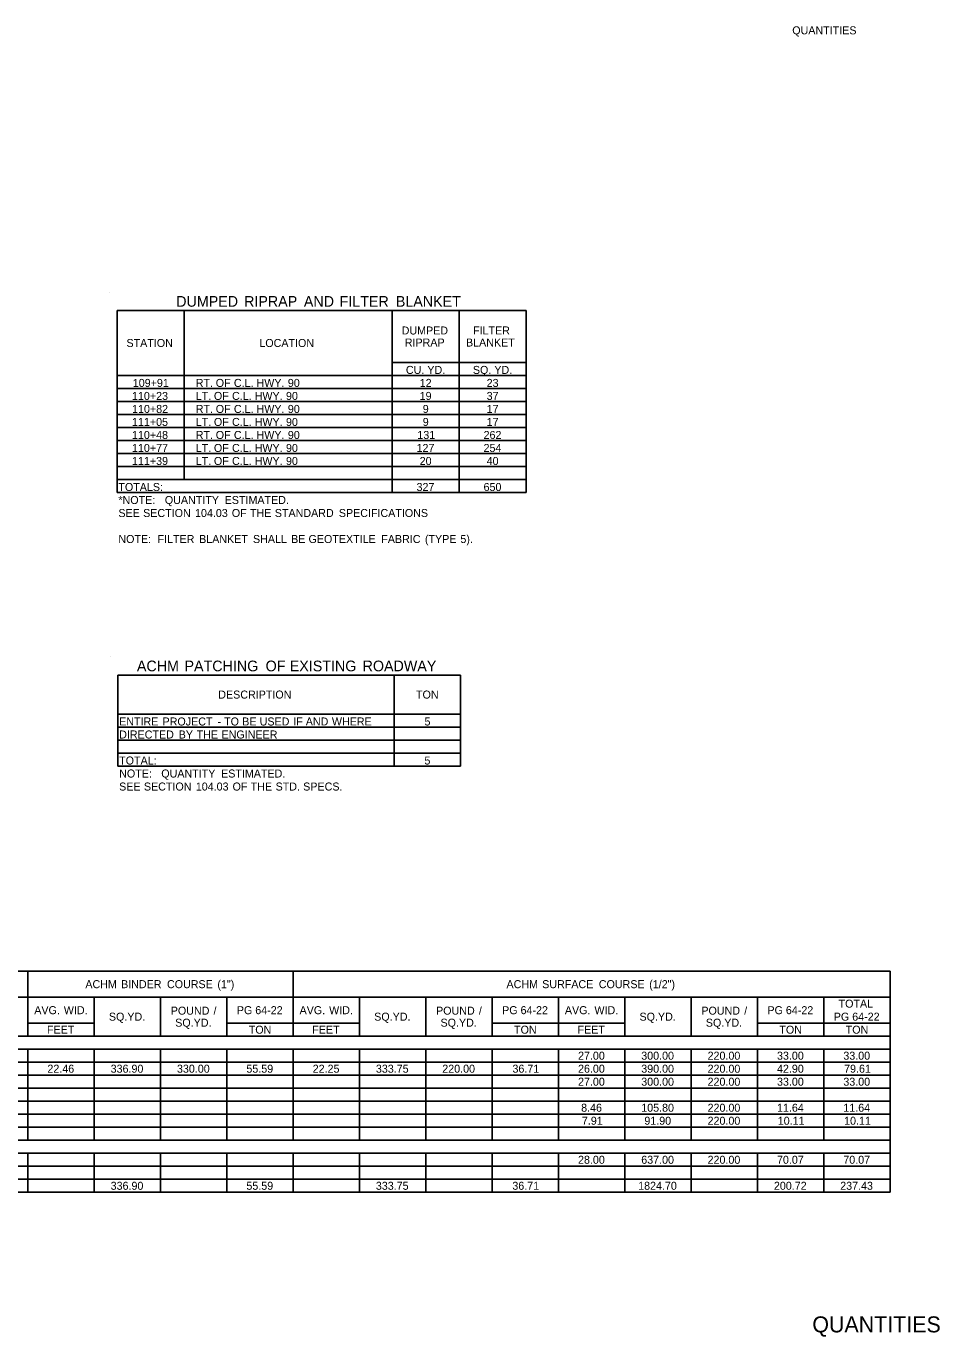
# Model space of a CAD drawing. Extents: x 120 to 5602, y 34 to 1048.
# Drawn here: x 2948 to 3633, y 34 to 1017 of the extents above; entities that cross this region are included whole.
import ezdxf

# ---------------------------------------------------------------- set-up
doc = ezdxf.new("R2010")
doc.units = 0
for name, color, linetype in [('Default', 7, 'Continuous'), ('R_Annotation', 7, 'Continuous'), ('R_Logo', 7, 'Continuous'), ('STAMP', 7, 'Continuous')]:
    doc.layers.add(name, color=color, linetype=linetype)

msp = doc.modelspace()

# ---------------------------------------------------------------- linework, layer by layer
at = {"layer": 'Default'}
for p, q in [((3015.73, 803.76), (3322.37, 803.76)), ((3015.73, 667.26), (3015.73, 803.76)), ((3015.73, 667.26), (3015.73, 803.76)), ((3065.95, 677.01), (3065.95, 803.76)), ((3221.95, 667.26), (3221.95, 803.76)), ((3272.16, 667.26), (3272.16, 803.76)), ((3322.37, 667.26), (3322.37, 803.76)), ((3322.37, 667.26), (3322.37, 803.76)), ((3221.95, 764.76), (3322.37, 764.76)), ((3015.73, 755.01), (3322.37, 755.01)), ((3065.95, 677.01), (3065.95, 755.01)), ((3221.95, 667.26), (3221.95, 755.01)), ((3015.73, 745.26), (3322.37, 745.26)), ((3015.73, 735.51), (3322.37, 735.51)), ((3015.73, 725.76), (3322.37, 725.76)), ((3015.73, 716.01), (3322.37, 716.01)), ((3015.73, 706.26), (3322.37, 706.26)), ((3015.73, 696.51), (3322.37, 696.51)), ((3015.73, 686.76), (3322.37, 686.76)), ((3015.73, 677.01), (3065.95, 677.01)), ((3015.73, 677.01), (3322.37, 677.01)), ((3015.73, 667.26), (3322.37, 667.26)), ((3016.31, 530.48), (3273.23, 530.48)), ((3016.31, 462.23), (3016.31, 530.48)), ((3016.31, 462.23), (3016.31, 530.48)), ((3223.5, 462.23), (3223.5, 530.48)), ((3273.23, 462.23), (3273.23, 530.48)), ((3016.31, 501.23), (3273.23, 501.23)), ((3223.5, 462.23), (3223.5, 501.23)), ((3273.23, 462.23), (3273.23, 501.23)), ((3016.31, 491.48), (3273.23, 491.48)), ((3016.31, 481.73), (3273.23, 481.73)), ((3016.31, 471.98), (3273.23, 471.98)), ((3016.31, 462.23), (3273.23, 462.23)), ((2103.12, 308.54), (3595.35, 308.54)), ((2948.93, 259.79), (2948.93, 308.54)), ((3147.83, 289.04), (3147.83, 308.54)), ((3147.83, 259.79), (3147.83, 308.54)), ((3595.35, 142.79), (3595.35, 308.54)), ((3595.35, 142.79), (3595.35, 308.54)), ((2493.6, 289.04), (3595.35, 289.04)), ((2998.65, 259.79), (2998.65, 289.04)), ((3048.38, 259.79), (3048.38, 289.04)), ((3098.1, 259.79), (3098.1, 289.04)), ((3197.55, 289.04), (3247.28, 289.04)), ((3197.55, 259.79), (3197.55, 289.04)), ((3247.28, 259.79), (3247.28, 289.04)), ((3297, 259.79), (3297, 289.04)), ((3346.73, 259.79), (3346.73, 289.04)), ((3396.45, 289.04), (3446.18, 289.04)), ((3396.45, 259.79), (3396.45, 289.04)), ((3446.18, 259.79), (3446.18, 289.04)), ((3495.9, 259.79), (3495.9, 289.04)), ((3545.63, 259.79), (3545.63, 289.04)), ((2948.93, 269.54), (2998.65, 269.54)), ((2998.65, 259.79), (2998.65, 269.54)), ((3098.1, 269.54), (3197.55, 269.54)), ((3147.83, 259.79), (3147.83, 269.54)), ((3197.55, 259.79), (3197.55, 269.54)), ((3297, 269.54), (3396.45, 269.54)), ((3346.73, 259.79), (3346.73, 269.54)), ((3396.45, 259.79), (3396.45, 269.54)), ((3495.9, 269.54), (3595.35, 269.54)), ((2103.12, 259.79), (3595.35, 259.79)), ((2849.48, 259.79), (2998.65, 259.79)), ((2998.65, 259.79), (3197.55, 259.79)), ((3197.55, 259.79), (3396.45, 259.79)), ((3396.45, 259.79), (3595.35, 259.79)), ((2103.12, 250.04), (3595.35, 250.04)), ((2948.93, 181.79), (2948.93, 250.04)), ((2948.93, 181.79), (2948.93, 250.04)), ((2998.65, 181.79), (2998.65, 250.04)), ((2998.65, 181.79), (2998.65, 250.04)), ((3048.38, 181.79), (3048.38, 250.04)), ((3048.38, 181.79), (3048.38, 250.04)), ((3098.1, 181.79), (3098.1, 250.04)), ((3098.1, 181.79), (3098.1, 250.04)), ((3147.83, 181.79), (3147.83, 250.04)), ((3147.83, 181.79), (3147.83, 250.04)), ((3197.55, 181.79), (3197.55, 250.04)), ((3197.55, 181.79), (3197.55, 250.04)), ((3247.28, 181.79), (3247.28, 250.04)), ((3247.28, 181.79), (3247.28, 250.04)), ((3297, 181.79), (3297, 250.04)), ((3297, 181.79), (3297, 250.04)), ((3346.73, 181.79), (3346.73, 250.04)), ((3346.73, 181.79), (3346.73, 250.04)), ((3396.45, 181.79), (3396.45, 250.04)), ((3396.45, 181.79), (3396.45, 250.04)), ((3446.18, 181.79), (3446.18, 250.04)), ((3446.18, 181.79), (3446.18, 250.04)), ((3495.9, 181.79), (3495.9, 250.04)), ((3495.9, 181.79), (3495.9, 250.04)), ((3545.63, 181.79), (3545.63, 250.04)), ((3545.63, 181.79), (3545.63, 250.04)), ((2103.12, 240.29), (3595.35, 240.29)), ((2103.12, 230.54), (3595.35, 230.54)), ((2103.12, 220.79), (3595.35, 220.79)), ((2103.12, 211.04), (3595.35, 211.04)), ((2103.12, 201.29), (3595.35, 201.29)), ((2103.12, 191.54), (3595.35, 191.54)), ((2103.12, 181.79), (3595.35, 181.79)), ((2103.12, 181.79), (3595.35, 181.79)), ((2103.12, 172.04), (3595.35, 172.04)), ((2948.93, 142.79), (2948.93, 172.04)), ((2948.93, 142.79), (2948.93, 172.04)), ((2998.65, 142.79), (2998.65, 172.04)), ((2998.65, 142.79), (2998.65, 172.04)), ((3048.38, 142.79), (3048.38, 172.04)), ((3048.38, 142.79), (3048.38, 172.04)), ((3098.1, 142.79), (3098.1, 172.04)), ((3098.1, 142.79), (3098.1, 172.04)), ((3147.83, 142.79), (3147.83, 172.04)), ((3147.83, 142.79), (3147.83, 172.04)), ((3197.55, 142.79), (3197.55, 172.04)), ((3197.55, 142.79), (3197.55, 172.04)), ((3247.28, 142.79), (3247.28, 172.04)), ((3247.28, 142.79), (3247.28, 172.04)), ((3297, 142.79), (3297, 172.04)), ((3297, 142.79), (3297, 172.04)), ((3346.73, 142.79), (3346.73, 172.04)), ((3346.73, 142.79), (3346.73, 172.04)), ((3396.45, 142.79), (3396.45, 172.04)), ((3396.45, 142.79), (3396.45, 172.04)), ((3446.18, 142.79), (3446.18, 172.04)), ((3446.18, 142.79), (3446.18, 172.04)), ((3495.9, 142.79), (3495.9, 172.04)), ((3495.9, 142.79), (3495.9, 172.04)), ((3545.63, 142.79), (3545.63, 172.04)), ((3545.63, 142.79), (3545.63, 172.04)), ((2103.12, 162.29), (3595.35, 162.29)), ((2103.12, 152.54), (3595.35, 152.54)), ((2103.12, 142.79), (3595.35, 142.79))]:
    msp.add_line(p, q, dxfattribs=at)
at = {"layer": 'STAMP'}
for p, q in [((3009.88, 817.41), (3009.88, 817.41)), ((3010.46, 544.13), (3010.46, 544.13))]:
    msp.add_line(p, q, dxfattribs=at)

# ---------------------------------------------------------------- texts
at = {"layer": 'Default'}
for s, height, p in [('DUMPED', 8, (3060.08, 806.59)), (' RIPRAP', 8, (3107.97, 806.59)), (' AND', 8, (3152.8, 806.59)), (' FILTER', 8, (3179.57, 806.59)), (' BLANKET', 8, (3221.74, 806.59)), ('DUMPED', 6, (3229.09, 785.76)), ('FILTER', 6, (3282.62, 785.76)), ('STATION', 6, (3022.78, 776.39)), ('LOCATION', 6, (3122.39, 776.39)), ('RIPRAP', 6, (3231.41, 776.76)), ('BLANKET', 6, (3277.32, 776.76)), ('CU.', 6, (3232.26, 756.21)), (' YD.', 6, (3246.12, 756.21)), ('SQ.', 6, (3282.47, 756.21)), (' YD.', 6, (3296.33, 756.21)), ('109+91', 6, (3027.51, 746.46)), ('RT.', 6, (3074.72, 746.46)), (' OF', 6, (3087.49, 746.46)), (' C.L.', 6, (3101.08, 746.46)), (' HWY.', 6, (3118.05, 746.46)), (' 90', 6, (3141.53, 746.46)), ('12', 6, (3242.61, 746.46)), ('23', 6, (3292.8, 746.46)), ('110+23', 6, (3026.93, 736.71)), ('LT.', 6, (3074.72, 736.71)), (' OF', 6, (3086.1, 736.71)), (' C.L.', 6, (3099.69, 736.71)), (' HWY.', 6, (3116.65, 736.71)), (' 90', 6, (3140.14, 736.71)), ('19', 6, (3242.58, 736.71)), ('37', 6, (3292.8, 736.71)), ('110+82', 6, (3026.97, 726.96)), ('RT.', 6, (3074.72, 726.96)), (' OF', 6, (3087.49, 726.96)), (' C.L.', 6, (3101.08, 726.96)), (' HWY.', 6, (3118.05, 726.96)), (' 90', 6, (3141.53, 726.96)), ('9', 6, (3244.91, 726.96)), ('17', 6, (3292.8, 726.96)), ('111+05', 6, (3026.91, 717.21)), ('LT.', 6, (3074.72, 717.21)), (' OF', 6, (3086.1, 717.21)), (' C.L.', 6, (3099.69, 717.21)), (' HWY.', 6, (3116.65, 717.21)), (' 90', 6, (3140.14, 717.21)), ('9', 6, (3244.91, 717.21)), ('17', 6, (3292.8, 717.21)), ('110+48', 6, (3026.93, 707.46)), ('RT.', 6, (3074.72, 707.46)), (' OF', 6, (3087.49, 707.46)), (' C.L.', 6, (3101.08, 707.46)), (' HWY.', 6, (3118.05, 707.46)), (' 90', 6, (3141.53, 707.46)), ('131', 6, (3240.83, 707.46)), ('262', 6, (3290.5, 707.46)), ('110+77', 6, (3026.93, 697.71)), ('LT.', 6, (3074.72, 697.71)), (' OF', 6, (3086.1, 697.71)), (' C.L.', 6, (3099.69, 697.71)), (' HWY.', 6, (3116.65, 697.71)), (' 90', 6, (3140.14, 697.71)), ('127', 6, (3240.25, 697.71)), ('254', 6, (3290.48, 697.71)), ('111+39', 6, (3026.93, 687.96)), ('LT.', 6, (3074.72, 687.96)), (' OF', 6, (3086.1, 687.96)), (' C.L.', 6, (3099.69, 687.96)), (' HWY.', 6, (3116.65, 687.96)), (' 90', 6, (3140.14, 687.96)), ('20', 6, (3242.59, 687.96)), ('40', 6, (3292.81, 687.96)), ('TOTALS:', 6, (3016.71, 668.46)), ('327', 6, (3240.25, 668.46)), ('650', 6, (3290.48, 668.46)), ('*NOTE:', 6, (3016.71, 658.71)), ('   QUANTITY', 6, (3044.86, 658.71)), (' ESTIMATED.', 6, (3094.17, 658.71)), ('SEE', 6, (3016.71, 648.96)), (' SECTION', 6, (3033.04, 648.96)), (' 104.03', 6, (3071.95, 648.96)), (' OF', 6, (3099.52, 648.96)), (' THE', 6, (3113.11, 648.96)), (' STANDARD', 6, (3131.76, 648.96)), (' SPECIFICATIONS', 6, (3179.76, 648.96)), ('NOTE:', 6, (3016.71, 629.46)), ('  FILTER', 6, (3041.6, 629.46)), (' BLANKET', 6, (3075.02, 629.46)), (' SHALL', 6, (3115.38, 629.46)), (' BE', 6, (3143.98, 629.46)), (' GEOTEXTILE', 6, (3157.04, 629.46)), (' FABRIC', 6, (3211.57, 629.46)), (' (TYPE', 6, (3244.31, 629.46)), (' 5).', 6, (3270.88, 629.46)), ('ACHM', 8, (3030.59, 533.31)), (' PATCHING', 8, (3063.32, 533.31)), (' OF', 8, (3124.12, 533.31)), (' EXISTING', 8, (3142.23, 533.31)), (' ROADWAY', 8, (3196.84, 533.31)), ('DESCRIPTION', 6, (3091.6, 512.86)), ('TON', 6, (3239.85, 512.86)), ('ENTIRE', 6, (3017.29, 492.68)), (' PROJECT', 6, (3047.59, 492.68)), (' -', 6, (3088.88, 492.68)), (' TO', 6, (3093.73, 492.68)), (' BE', 6, (3107.33, 492.68)), (' USED', 6, (3120.4, 492.68)), (' IF', 6, (3145.57, 492.68)), (' AND', 6, (3154.96, 492.68)), (' WHERE', 6, (3174.55, 492.68)), ('5', 6, (3246.2, 492.68)), ('DIRECTED', 6, (3017.29, 482.93)), (' BY', 6, (3059.7, 482.93)), (' THE', 6, (3073.15, 482.93)), (' ENGINEER', 6, (3091.8, 482.93)), ('TOTAL:', 6, (3017.29, 463.43)), ('5', 6, (3246.16, 463.43)), ('NOTE:', 6, (3017.29, 453.68)), ('   QUANTITY', 6, (3042.18, 453.68)), (' ESTIMATED.', 6, (3091.48, 453.68)), ('SEE', 6, (3017.29, 443.93)), (' SECTION', 6, (3033.62, 443.93)), (' 104.03', 6, (3072.53, 443.93)), (' OF', 6, (3100.1, 443.93)), (' THE', 6, (3113.69, 443.93)), (' STD.', 6, (3132.34, 443.93)), (' SPECS.', 6, (3153.03, 443.93)), ('ACHM', 6, (2991.95, 295.79)), (' BINDER', 6, (3016.5, 295.79)), (' COURSE', 6, (3050.92, 295.79)), (' (1")', 6, (3088.71, 295.79)), ('ACHM', 6, (3307.66, 295.79)), (' SURFACE', 6, (3332.21, 295.79)), (' COURSE', 6, (3374.65, 295.79)), (' (1/2")', 6, (3412.43, 295.79)), ('TOTAL', 6, (3556.65, 281.17)), ('AVG.', 6, (2953.65, 276.29)), (' WID.', 6, (2973.57, 276.29)), ('SQ.YD.', 6, (3009.6, 271.42)), ('POUND', 6, (3055.98, 275.92)), (' /', 6, (3085.84, 275.92)), ('PG', 6, (3105.5, 276.29)), (' 64-22', 6, (3117.1, 276.29)), ('AVG.', 6, (3152.55, 276.29)), (' WID.', 6, (3172.47, 276.29)), ('SQ.YD.', 6, (3208.5, 271.42)), ('POUND', 6, (3254.88, 275.92)), (' /', 6, (3284.74, 275.92)), ('PG', 6, (3304.4, 276.29)), (' 64-22', 6, (3316, 276.29)), ('AVG.', 6, (3351.45, 276.29)), (' WID.', 6, (3371.37, 276.29)), ('SQ.YD.', 6, (3407.4, 271.42)), ('POUND', 6, (3453.78, 275.92)), (' /', 6, (3483.64, 275.92)), ('PG', 6, (3503.3, 276.29)), (' 64-22', 6, (3514.9, 276.29)), ('PG', 6, (3553.02, 271.42)), (' 64-22', 6, (3564.63, 271.42)), ('FEET', 6, (2963.16, 261.67)), ('SQ.YD.', 6, (3059.32, 266.92)), ('TON', 6, (3114.45, 261.67)), ('FEET', 6, (3162.06, 261.67)), ('SQ.YD.', 6, (3258.22, 266.92)), ('TON', 6, (3313.35, 261.67)), ('FEET', 6, (3360.96, 261.67)), ('SQ.YD.', 6, (3457.12, 266.92)), ('TON', 6, (3512.25, 261.67)), ('TON', 6, (3561.98, 261.67)), ('27.00', 6, (3361.31, 242.17)), ('300.00', 6, (3408.7, 242.17)), ('220.00', 6, (3458.43, 242.17)), ('33.00', 6, (3510.48, 242.17)), ('33.00', 6, (3560.21, 242.17)), ('22.46', 6, (2963.5, 232.42)), ('336.90', 6, (3010.9, 232.42)), ('330.00', 6, (3060.63, 232.42)), ('55.59', 6, (3112.67, 232.42)), ('22.25', 6, (3162.38, 232.42)), ('333.75', 6, (3209.77, 232.42)), ('220.00', 6, (3259.53, 232.42)), ('36.71', 6, (3312.15, 232.42)), ('26.00', 6, (3361.31, 232.42)), ('390.00', 6, (3408.7, 232.42)), ('220.00', 6, (3458.43, 232.42)), ('42.90', 6, (3510.48, 232.42)), ('79.61', 6, (3560.78, 232.42)), ('27.00', 6, (3361.31, 222.67)), ('300.00', 6, (3408.7, 222.67)), ('220.00', 6, (3458.43, 222.67)), ('33.00', 6, (3510.48, 222.67)), ('33.00', 6, (3560.21, 222.67)), ('8.46', 6, (3363.63, 203.17)), ('105.80', 6, (3408.7, 203.17)), ('220.00', 6, (3458.43, 203.17)), ('11.64', 6, (3510.49, 203.17)), ('11.64', 6, (3560.21, 203.17)), ('7.91', 6, (3364.21, 193.42)), ('91.90', 6, (3411.03, 193.42)), ('220.00', 6, (3458.43, 193.42)), ('10.11', 6, (3511.05, 193.42)), ('10.11', 6, (3560.78, 193.42)), ('28.00', 6, (3361.31, 164.17)), ('637.00', 6, (3408.7, 164.17)), ('220.00', 6, (3458.43, 164.17)), ('70.07', 6, (3510.47, 164.17)), ('70.07', 6, (3560.2, 164.17)), ('336.90', 6, (3010.91, 144.67)), ('55.59', 6, (3112.68, 144.67)), ('333.75', 6, (3209.73, 144.67)), ('36.71', 6, (3312.06, 144.67)), ('1824.70', 6, (3406.38, 144.67)), ('200.72', 6, (3508.16, 144.67)), ('237.43', 6, (3557.86, 144.67))]:
    msp.add_text(s, height=height, dxfattribs=at).set_placement(p)
at = {"layer": 'R_Annotation'}
msp.add_text('QUANTITIES', height=12, dxfattribs=at).set_placement((3536.97, 37.77))
at = {"layer": 'R_Logo'}
msp.add_text('QUANTITIES', height=6, dxfattribs=at).set_placement((3521.92, 1010.75))

doc.saveas('drawing.dxf')
